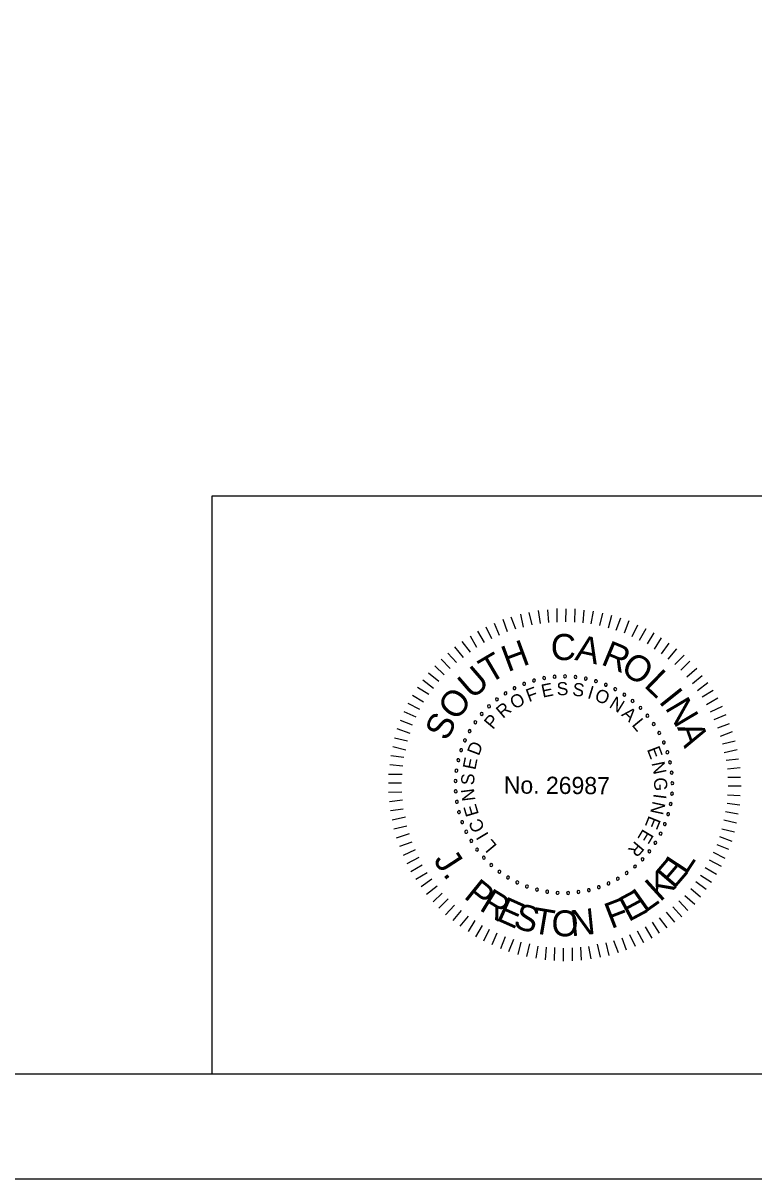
# Model space of a CAD drawing. Extents: x -121.2 to -24.9, y 6.4 to 65.5.
# Drawn here: x -63.2 to -53.93, y 6.35 to 21.02 of the extents above; entities that cross this region are included whole.
import ezdxf

# ---------------------------------------------------------------- set-up
doc = ezdxf.new("R2010")
doc.units = 0
for name, color, linetype in [('BR_BORDER LINES', 7, 'Continuous'), ('BR_TEXT', 7, 'Continuous'), ('Level 31', 7, 'Continuous')]:
    doc.layers.add(name, color=color, linetype=linetype)

msp = doc.modelspace()

# ---------------------------------------------------------------- linework, layer by layer
at = {"layer": 'BR_BORDER LINES'}
for p, q in [((-60.804, 15.017), (-46.496, 15.017)), ((-60.804, 7.683), (-60.804, 15.017)), ((-116.272, 7.683), (-26.496, 7.683))]:
    msp.add_line(p, q, dxfattribs=at)
at = {"layer": 'BR_TEXT'}
for p, q in [((-56.855, 13.352), (-56.89, 13.515)), ((-56.744, 13.379), (-56.782, 13.537)), ((-56.639, 13.398), (-56.663, 13.561)), ((-56.534, 13.409), (-56.544, 13.572)), ((-56.428, 13.415), (-56.427, 13.587)), ((-56.316, 13.421), (-56.315, 13.586)), ((-56.204, 13.413), (-56.198, 13.585)), ((-56.097, 13.405), (-56.084, 13.568)), ((-55.994, 13.393), (-55.965, 13.555)), ((-55.886, 13.372), (-55.848, 13.529)), ((-55.777, 13.343), (-55.734, 13.505)), ((-57.258, 13.202), (-57.328, 13.352)), ((-57.16, 13.247), (-57.223, 13.396)), ((-57.056, 13.292), (-57.112, 13.448)), ((-56.951, 13.326), (-57.009, 13.479)), ((-55.679, 13.315), (-55.62, 13.468)), ((-55.574, 13.28), (-55.515, 13.435)), ((-55.478, 13.233), (-55.403, 13.381)), ((-57.445, 13.092), (-57.526, 13.236)), ((-57.35, 13.155), (-57.432, 13.3)), ((-55.382, 13.187), (-55.298, 13.335)), ((-55.282, 13.138), (-55.196, 13.281)), ((-55.193, 13.073), (-55.103, 13.216)), ((-57.617, 12.967), (-57.724, 13.101)), ((-57.528, 13.035), (-57.632, 13.171)), ((-55.104, 13.015), (-55.007, 13.149)), ((-55.018, 12.946), (-54.909, 13.078)), ((-57.783, 12.829), (-57.901, 12.947)), ((-57.705, 12.902), (-57.816, 13.021)), ((-54.934, 12.879), (-54.818, 12.997)), ((-54.859, 12.805), (-54.743, 12.921)), ((-57.929, 12.663), (-58.061, 12.767)), ((-57.862, 12.747), (-57.978, 12.86)), ((-54.784, 12.722), (-54.657, 12.833)), ((-57.998, 12.574), (-58.13, 12.681)), ((-54.712, 12.636), (-54.587, 12.738)), ((-54.648, 12.547), (-54.517, 12.651)), ((-58.121, 12.399), (-58.264, 12.485)), ((-58.056, 12.497), (-58.2, 12.585)), ((-54.589, 12.468), (-54.449, 12.554)), ((-58.168, 12.308), (-58.318, 12.382)), ((-54.531, 12.37), (-54.388, 12.453)), ((-54.483, 12.278), (-54.329, 12.35)), ((-58.214, 12.21), (-58.367, 12.278)), ((-54.436, 12.179), (-54.284, 12.244)), ((-58.294, 12), (-58.458, 12.061)), ((-58.261, 12.107), (-58.416, 12.166)), ((-54.391, 12.075), (-54.24, 12.131)), ((-58.327, 11.904), (-58.489, 11.945)), ((-54.355, 11.968), (-54.202, 12.026)), ((-54.329, 11.871), (-54.168, 11.909)), ((-58.346, 11.792), (-58.512, 11.835)), ((-54.307, 11.759), (-54.146, 11.799)), ((-58.386, 11.587), (-58.551, 11.606)), ((-58.374, 11.696), (-58.536, 11.718)), ((-54.285, 11.663), (-54.127, 11.682)), ((-58.394, 11.481), (-58.566, 11.483)), ((-54.267, 11.553), (-54.105, 11.57)), ((-54.264, 11.447), (-54.103, 11.446)), ((-58.4, 11.372), (-58.567, 11.373)), ((-54.258, 11.338), (-54.095, 11.336)), ((-58.396, 11.257), (-58.568, 11.254)), ((-58.39, 11.154), (-58.555, 11.135)), ((-54.266, 11.223), (-54.105, 11.217)), ((-58.379, 11.044), (-58.542, 11.02)), ((-54.29, 11.011), (-54.132, 10.984)), ((-54.271, 11.12), (-54.109, 11.098)), ((-58.353, 10.939), (-58.52, 10.904)), ((-54.314, 10.905), (-54.154, 10.867)), ((-58.335, 10.826), (-58.498, 10.789)), ((-58.304, 10.728), (-58.469, 10.672)), ((-54.338, 10.793), (-54.178, 10.753)), ((-58.273, 10.625), (-58.429, 10.569)), ((-54.403, 10.593), (-54.253, 10.534)), ((-54.366, 10.695), (-54.213, 10.637)), ((-58.228, 10.526), (-58.382, 10.454)), ((-58.183, 10.429), (-58.335, 10.35)), ((-54.45, 10.495), (-54.3, 10.42)), ((-58.138, 10.331), (-58.283, 10.247)), ((-54.548, 10.301), (-54.407, 10.215)), ((-54.499, 10.399), (-54.346, 10.318)), ((-58.075, 10.232), (-58.22, 10.148)), ((-58.018, 10.153), (-58.152, 10.056)), ((-54.668, 10.126), (-54.539, 10.026)), ((-54.608, 10.203), (-54.469, 10.117)), ((-57.95, 10.064), (-58.084, 9.959)), ((-57.885, 9.974), (-58.002, 9.865)), ((-54.733, 10.037), (-54.61, 9.931)), ((-57.808, 9.904), (-57.927, 9.784)), ((-54.883, 9.88), (-54.77, 9.758)), ((-54.807, 9.948), (-54.682, 9.837)), ((-57.73, 9.824), (-57.844, 9.701)), ((-57.644, 9.754), (-57.753, 9.629)), ((-57.555, 9.685), (-57.662, 9.558)), ((-55.044, 9.733), (-54.938, 9.606)), ((-54.959, 9.801), (-54.846, 9.676)), ((-57.473, 9.627), (-57.557, 9.488)), ((-57.38, 9.567), (-57.464, 9.423)), ((-55.311, 9.55), (-55.228, 9.405)), ((-55.222, 9.608), (-55.134, 9.468)), ((-55.132, 9.665), (-55.037, 9.536)), ((-57.289, 9.513), (-57.361, 9.365)), ((-57.191, 9.467), (-57.256, 9.319)), ((-57.088, 9.42), (-57.147, 9.27)), ((-56.983, 9.387), (-57.044, 9.232)), ((-55.606, 9.408), (-55.55, 9.256)), ((-55.509, 9.453), (-55.437, 9.304)), ((-55.413, 9.498), (-55.331, 9.348)), ((-56.888, 9.354), (-56.925, 9.197)), ((-56.778, 9.335), (-56.818, 9.171)), ((-56.673, 9.305), (-56.699, 9.149)), ((-56.568, 9.292), (-56.58, 9.128)), ((-56.462, 9.285), (-56.464, 9.12)), ((-56.35, 9.277), (-56.352, 9.114)), ((-56.238, 9.283), (-56.235, 9.118)), ((-56.131, 9.289), (-56.121, 9.124)), ((-56.028, 9.299), (-56.001, 9.143)), ((-55.92, 9.328), (-55.884, 9.163)), ((-55.81, 9.346), (-55.77, 9.187)), ((-55.711, 9.377), (-55.655, 9.221))]:
    msp.add_line(p, q, dxfattribs=at)
for centre, start, end in [((-56.847, 12.632), 21.6807, 201.6807), ((-56.847, 12.632), 201.6807, 21.6807), ((-56.721, 12.674), 16.1422, 196.1422), ((-56.721, 12.674), 196.1422, 16.1422), ((-56.592, 12.705), 10.6038, 190.6038), ((-56.592, 12.705), 190.6038, 10.6038), ((-56.46, 12.723), 5.0653, 185.0653), ((-56.46, 12.723), 185.0653, 5.0653), ((-56.328, 12.728), 359.5268, 179.5268), ((-56.328, 12.728), 179.5268, 359.5268), ((-56.195, 12.72), 353.9884, 173.9884), ((-56.195, 12.72), 173.9884, 353.9884), ((-56.064, 12.699), 348.4499, 168.4499), ((-56.064, 12.699), 168.4499, 348.4499), ((-55.935, 12.666), 162.9114, 342.9114), ((-55.935, 12.666), 342.9114, 162.9114), ((-55.81, 12.621), 157.373, 337.373), ((-55.81, 12.621), 337.373, 157.373), ((-57.083, 12.511), 32.7576, 212.7576), ((-57.083, 12.511), 212.7576, 32.7576), ((-56.968, 12.577), 27.2191, 207.2191), ((-56.968, 12.577), 207.2191, 27.2191), ((-55.69, 12.564), 151.8345, 331.8345), ((-55.69, 12.564), 331.8345, 151.8345), ((-55.576, 12.495), 146.2961, 326.2961), ((-55.576, 12.495), 326.2961, 146.2961), ((-57.292, 12.347), 43.8345, 223.8345), ((-57.292, 12.347), 223.8345, 43.8345), ((-57.192, 12.434), 38.2961, 218.2961), ((-57.192, 12.434), 218.2961, 38.2961), ((-55.47, 12.416), 140.7576, 320.7576), ((-55.47, 12.416), 320.7576, 140.7576), ((-55.371, 12.327), 135.2191, 315.2191), ((-55.371, 12.327), 315.2191, 135.2191), ((-57.384, 12.25), 49.373, 229.373), ((-57.384, 12.25), 229.373, 49.373), ((-55.282, 12.229), 129.6807, 309.6807), ((-55.282, 12.229), 309.6807, 129.6807), ((-57.537, 12.033), 60.4499, 240.4499), ((-57.537, 12.033), 240.4499, 60.4499), ((-57.465, 12.145), 54.9114, 234.9114), ((-57.465, 12.145), 234.9114, 54.9114), ((-55.202, 12.122), 124.1422, 304.1422), ((-55.202, 12.122), 304.1422, 124.1422), ((-55.133, 12.009), 298.6038, 118.6038), ((-57.597, 11.915), 65.9884, 245.9884), ((-57.597, 11.915), 245.9884, 65.9884), ((-55.133, 12.009), 118.6038, 298.6038), ((-55.075, 11.889), 113.0653, 293.0653), ((-55.075, 11.889), 293.0653, 113.0653), ((-57.645, 11.791), 71.5268, 251.5268), ((-57.645, 11.791), 251.5268, 71.5268), ((-55.029, 11.764), 107.5268, 287.5268), ((-55.029, 11.764), 287.5268, 107.5268), ((-57.681, 11.663), 77.0653, 257.0653), ((-57.681, 11.663), 257.0653, 77.0653), ((-54.996, 11.636), 101.9884, 281.9884), ((-54.996, 11.636), 281.9884, 101.9884), ((-57.705, 11.532), 82.6038, 262.6038), ((-57.705, 11.532), 262.6038, 82.6038), ((-54.975, 11.504), 96.4499, 276.4499), ((-54.975, 11.504), 276.4499, 96.4499), ((-57.716, 11.4), 88.1422, 268.1422), ((-57.716, 11.4), 268.1422, 88.1422), ((-54.967, 11.372), 90.9114, 270.9114), ((-54.967, 11.372), 270.9114, 90.9114), ((-57.714, 11.267), 93.6807, 273.6807), ((-57.7, 11.135), 99.2191, 279.2191), ((-57.714, 11.267), 273.6807, 93.6807), ((-57.7, 11.135), 279.2191, 99.2191), ((-54.971, 11.239), 85.373, 265.373), ((-54.971, 11.239), 265.373, 85.373), ((-57.672, 11.005), 104.7576, 284.7576), ((-57.672, 11.005), 284.7576, 104.7576), ((-54.989, 11.107), 79.8345, 259.8345), ((-54.989, 11.107), 259.8345, 79.8345), ((-57.632, 10.878), 110.2961, 290.2961), ((-57.632, 10.878), 290.2961, 110.2961), ((-55.061, 10.852), 68.7576, 248.7576), ((-55.061, 10.852), 248.7576, 68.7576), ((-55.019, 10.978), 74.2961, 254.2961), ((-55.019, 10.978), 254.2961, 74.2961), ((-57.581, 10.756), 115.8345, 295.8345), ((-57.581, 10.756), 295.8345, 115.8345), ((-55.115, 10.731), 63.2191, 243.2191), ((-55.115, 10.731), 243.2191, 63.2191), ((-57.517, 10.639), 121.373, 301.373), ((-57.517, 10.639), 301.373, 121.373), ((-55.181, 10.615), 57.6807, 237.6807), ((-55.181, 10.615), 237.6807, 57.6807), ((-57.443, 10.529), 126.9114, 306.9114), ((-57.443, 10.529), 306.9114, 126.9114), ((-57.358, 10.426), 132.4499, 312.4499), ((-57.358, 10.426), 312.4499, 132.4499), ((-55.344, 10.406), 46.6038, 226.6038), ((-55.344, 10.406), 226.6038, 46.6038), ((-55.258, 10.507), 52.1422, 232.1422), ((-55.258, 10.507), 232.1422, 52.1422), ((-57.264, 10.333), 137.9884, 317.9884), ((-57.264, 10.333), 317.9884, 137.9884), ((-57.161, 10.248), 323.5268, 143.5268), ((-55.44, 10.314), 41.0653, 221.0653), ((-55.44, 10.314), 221.0653, 41.0653), ((-57.161, 10.248), 143.5268, 323.5268), ((-57.051, 10.174), 149.0653, 329.0653), ((-57.051, 10.174), 329.0653, 149.0653), ((-56.934, 10.112), 334.6038, 154.6038), ((-55.657, 10.16), 29.9884, 209.9884), ((-55.657, 10.16), 209.9884, 29.9884), ((-55.545, 10.232), 35.5268, 215.5268), ((-55.545, 10.232), 215.5268, 35.5268), ((-56.934, 10.112), 154.6038, 334.6038), ((-56.811, 10.06), 160.1422, 340.1422), ((-56.811, 10.06), 340.1422, 160.1422), ((-56.684, 10.021), 345.6807, 165.6807), ((-56.684, 10.021), 165.6807, 345.6807), ((-56.554, 9.994), 351.2191, 171.2191), ((-56.554, 9.994), 171.2191, 351.2191), ((-56.422, 9.98), 356.7576, 176.7576), ((-56.422, 9.98), 176.7576, 356.7576), ((-56.289, 9.978), 2.2961, 182.2961), ((-56.289, 9.978), 182.2961, 2.2961), ((-56.157, 9.99), 7.8345, 187.8345), ((-56.157, 9.99), 187.8345, 7.8345), ((-56.026, 10.014), 13.373, 193.373), ((-56.026, 10.014), 193.373, 13.373), ((-55.899, 10.051), 18.9114, 198.9114), ((-55.899, 10.051), 198.9114, 18.9114), ((-55.775, 10.1), 24.4499, 204.4499), ((-55.775, 10.1), 204.4499, 24.4499)]:
    msp.add_arc(centre, 0.0187, start, end, dxfattribs=at)
at = {"layer": 'Level 31'}
msp.add_lwpolyline([(-121.161, 6.35), (-25.161, 6.35), (-25.161, 65.017), (-121.161, 65.017)], close=True, dxfattribs=at)

# ---------------------------------------------------------------- texts
at = {"layer": 'BR_TEXT'}
for s, height, rotation, p in [('C', 0.331, 359.5482, (-56.51, 12.935)), ('A', 0.331, 348.1981, (-56.213, 12.937)), ('H', 0.331, 20.3637, (-57.055, 12.779)), ('R', 0.331, 337.4344, (-55.884, 12.884)), ('T', 0.331, 30.4992, (-57.29, 12.626)), ('O', 0.33, 326.5869, (-55.638, 12.786)), ('U', 0.331, 40.8022, (-57.506, 12.426)), ('L', 0.331, 315.9488, (-55.338, 12.605)), ('E', 0.166, 11.4103, (-56.611, 12.456)), ('S', 0.166, 2.208, (-56.431, 12.485)), ('S', 0.166, 352.6608, (-56.241, 12.485)), ('O', 0.331, 52.0267, (-57.705, 12.149)), ('O', 0.166, 30.8477, (-56.965, 12.302)), ('F', 0.166, 20.6127, (-56.785, 12.398)), ('I', 0.166, 343.1136, (-56.053, 12.453)), ('O', 0.166, 338.4392, (-55.964, 12.426)), ('N', 0.166, 328.2042, (-55.778, 12.342)), ('I', 0.331, 308.6613, (-55.148, 12.407)), ('R', 0.166, 40.3949, (-57.115, 12.185)), ('N', 0.331, 300.7037, (-55.066, 12.329)), ('S', 0.33, 63.2511, (-57.826, 11.894)), ('P', 0.166, 49.9421, (-57.243, 12.045)), ('A', 0.166, 318.657, (-55.621, 12.235)), ('L', 0.166, 309.4546, (-55.488, 12.109)), ('A', 0.331, 289.4792, (-54.908, 12.081)), ('D', 0.166, 69.0364, (-57.421, 11.711)), ('E', 0.166, 291.049, (-55.291, 11.801)), ('E', 0.166, 78.2388, (-57.466, 11.533)), ('N', 0.166, 281.8466, (-55.232, 11.628)), ('S', 0.166, 87.786, (-57.481, 11.344)), ('No. 26987', 0.218, 359.5268, (-57.105, 11.241)), ('N', 0.166, 97.3332, (-57.464, 11.154)), ('G', 0.166, 272.2995, (-55.201, 11.441)), ('I', 0.166, 262.4084, (-55.202, 11.244)), ('E', 0.166, 106.5355, (-57.419, 10.977)), ('N', 0.166, 257.7339, (-55.214, 11.151)), ('C', 0.166, 116.4266, (-57.339, 10.797)), ('E', 0.166, 248.1867, (-55.262, 10.968)), ('I', 0.166, 121.1011, (-57.291, 10.717)), ('E', 0.166, 238.9844, (-55.337, 10.8)), ('L', 0.166, 129.9595, (-57.183, 10.578)), ('R', 0.166, 229.782, (-55.437, 10.647)), ('J', 0.329, 302.9559, (-58.004, 10.395)), ('E', 0.329, 49.3639, (-54.948, 10.017)), ('L', 0.329, 56.4247, (-54.795, 10.198)), ('K', 0.329, 42.3031, (-55.122, 9.857)), ('.', 0.329, 309.3974, (-57.886, 10.214)), ('P', 0.329, 321.1035, (-57.624, 9.923)), ('R', 0.329, 328.5359, (-57.428, 9.768)), ('E', 0.329, 28.1814, (-55.523, 9.606)), ('L', 0.329, 35.2422, (-55.315, 9.719)), ('E', 0.329, 335.9684, (-57.215, 9.64)), ('S', 0.329, 343.0292, (-56.998, 9.545)), ('F', 0.329, 21.1206, (-55.743, 9.519)), ('T', 0.329, 350.4617, (-56.759, 9.474)), ('O', 0.329, 358.1419, (-56.504, 9.434)), ('N', 0.329, 5.8221, (-56.247, 9.428))]:
    msp.add_text(s, height=height, rotation=rotation, dxfattribs=at).set_placement(p)

doc.saveas('drawing.dxf')
